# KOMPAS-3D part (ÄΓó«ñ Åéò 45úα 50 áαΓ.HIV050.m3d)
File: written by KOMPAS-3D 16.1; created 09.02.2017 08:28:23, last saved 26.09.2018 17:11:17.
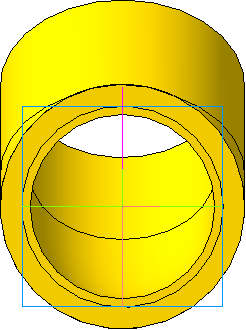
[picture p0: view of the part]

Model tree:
1. Эскиз:1
2. Эскиз:24
3. Кинематическая операция:1
4. Эскиз:25
5. Вырезать кинематический элемент:1
6. Эскиз:26
7. Вырезать элемент выдавливания:9
     Расстояние 1 = 31
8. Эскиз:27
9. Вырезать элемент выдавливания:10
     Расстояние 1 = 31

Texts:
  Отвод ПВХ 45гр 50 арт.HIV050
